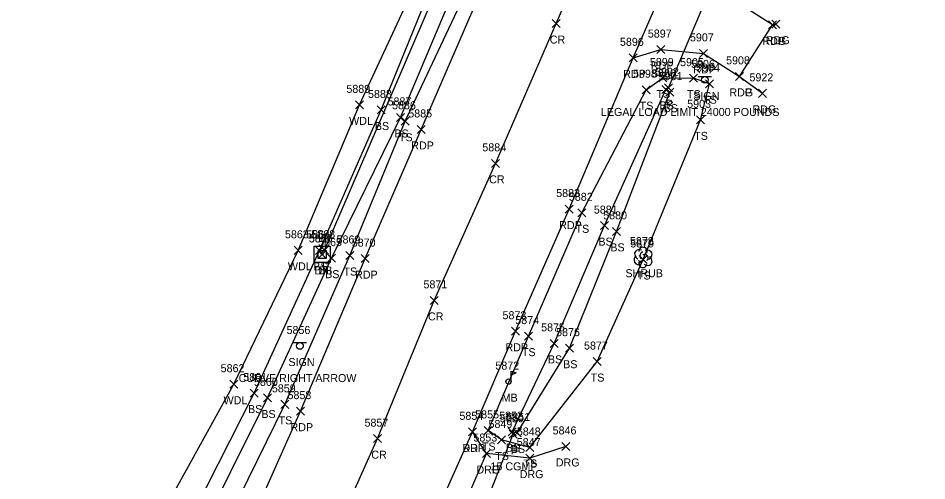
# Model space of a CAD drawing. Extents: x 1611797 to 1633212, y 298978 to 305475.
# Drawn here: x 1622594.7 to 1622821.6, y 301530.3 to 301645.8 of the extents above; entities that cross this region are included whole.
import ezdxf

# ---------------------------------------------------------------- set-up
doc = ezdxf.new("R2010")
doc.units = 0
for name, color, linetype in [('D_A', 7, 'Continuous'), ('D_C', 7, 'Continuous'), ('D_I', 7, 'Continuous'), ('D_TIC', 7, 'Continuous'), ('DCP', 7, 'Continuous'), ('DS', 7, 'Continuous'), ('L_A', 7, 'Continuous'), ('L_I', 7, 'Continuous'), ('L_TIC', 7, 'Continuous'), ('LAWA', 7, 'Continuous'), ('LELB', 7, 'Continuous'), ('LMB', 7, 'Continuous'), ('LSH', 7, 'Continuous'), ('P_A', 7, 'Continuous'), ('P_I', 7, 'Continuous'), ('P_TIC', 7, 'Continuous'), ('PET', 7, 'Continuous'), ('PEU', 7, 'Continuous'), ('PRC', 7, 'Continuous'), ('R_A', 7, 'Continuous'), ('R_I', 7, 'Continuous'), ('R_TIC', 7, 'Continuous'), ('RDG', 7, 'Continuous'), ('RDP', 7, 'Continuous'), ('S_A', 7, 'Continuous'), ('S_C', 7, 'Continuous'), ('S_I', 7, 'Continuous'), ('SSGN', 7, 'Continuous')]:
    doc.layers.add(name, color=color, linetype=linetype)

msp = doc.modelspace()

# ---------------------------------------------------------------- linework, layer by layer
at = {"layer": 'D_TIC'}
for points in [[(1622756.09, 301627.39), (1622758.09, 301629.39)], [(1622758.09, 301627.39), (1622756.09, 301629.39)], [(1622669.61, 301585.77), (1622671.61, 301587.77)], [(1622671.61, 301585.77), (1622669.61, 301587.77)], [(1622670.2, 301586.84), (1622672.2, 301588.84)], [(1622672.2, 301586.84), (1622670.2, 301588.84)], [(1622717.35, 301540.87), (1622719.35, 301542.87)], [(1622719.35, 301540.87), (1622717.35, 301542.87)]]:
    msp.add_lwpolyline(points, dxfattribs=at)
at = {"layer": 'DCP'}
for points in [[(1622671.2, 301587.84), (1622827.38, 301950.3)], [(1622757.09, 301628.39), (1622774.51, 301669.44)], [(1622708.82, 301517.78), (1622718.35, 301541.87)]]:
    msp.add_lwpolyline(points, dxfattribs=at)
at = {"layer": 'DS'}
for p, q in [((1622668.61, 301588.8), (1622672.61, 301588.8)), ((1622668.61, 301584.8), (1622668.61, 301588.8)), ((1622669.61, 301585.8), (1622669.61, 301587.8)), ((1622669.61, 301587.8), (1622671.61, 301587.8)), ((1622671.61, 301587.8), (1622671.61, 301585.8)), ((1622672.61, 301588.8), (1622672.61, 301584.8)), ((1622671.61, 301585.8), (1622669.61, 301585.8)), ((1622670.62, 301586.81), (1622670.62, 301586.81)), ((1622670.62, 301586.81), (1622670.62, 301586.81)), ((1622672.61, 301584.8), (1622668.61, 301584.8))]:
    msp.add_line(p, q, dxfattribs=at)
at = {"layer": 'L_TIC'}
for points in [[(1622754.72, 301629.83), (1622756.72, 301631.83)], [(1622756.72, 301629.83), (1622754.72, 301631.83)], [(1622762.33, 301629.79), (1622764.33, 301631.79)], [(1622764.33, 301629.79), (1622762.33, 301631.79)], [(1622762.33, 301629.79), (1622764.33, 301631.79)], [(1622764.33, 301629.79), (1622762.33, 301631.79)], [(1622750.51, 301626.91), (1622752.51, 301628.91)], [(1622752.51, 301626.91), (1622750.51, 301628.91)], [(1622755.42, 301626.98), (1622757.42, 301628.98)], [(1622757.42, 301626.98), (1622755.42, 301628.98)], [(1622766.34, 301628.41), (1622768.34, 301630.41)], [(1622768.34, 301628.41), (1622766.34, 301630.41)], [(1622756.45, 301626.29), (1622758.45, 301628.29)], [(1622758.45, 301626.29), (1622756.45, 301628.29)], [(1622756.45, 301626.29), (1622758.45, 301628.29)], [(1622758.45, 301626.29), (1622756.45, 301628.29)], [(1622678.92, 301623.12), (1622680.92, 301625.12)], [(1622680.92, 301623.12), (1622678.92, 301625.12)], [(1622684.32, 301621.84), (1622686.32, 301623.84)], [(1622686.32, 301621.84), (1622684.32, 301623.84)], [(1622689.2, 301619.98), (1622691.2, 301621.98)], [(1622691.2, 301619.98), (1622689.2, 301621.98)], [(1622690.37, 301619.02), (1622692.37, 301621.02)], [(1622692.37, 301619.02), (1622690.37, 301621.02)], [(1622764.11, 301619.38), (1622766.11, 301621.38)], [(1622766.11, 301619.38), (1622764.11, 301621.38)], [(1622734.48, 301596.17), (1622736.48, 301598.17)], [(1622736.48, 301596.17), (1622734.48, 301598.17)], [(1622740.16, 301592.97), (1622742.16, 301594.97)], [(1622742.16, 301592.97), (1622740.16, 301594.97)], [(1622743.14, 301591.54), (1622745.14, 301593.54)], [(1622745.14, 301591.54), (1622743.14, 301593.54)], [(1622663.62, 301586.8), (1622665.62, 301588.8)], [(1622665.62, 301586.8), (1622663.62, 301588.8)], [(1622668.95, 301586.77), (1622670.95, 301588.77)], [(1622670.95, 301586.77), (1622668.95, 301588.77)], [(1622671.9, 301584.85), (1622673.9, 301586.85)], [(1622673.9, 301584.85), (1622671.9, 301586.85)], [(1622676.51, 301585.51), (1622678.51, 301587.51)], [(1622678.51, 301585.51), (1622676.51, 301587.51)], [(1622749.82, 301584.52), (1622751.82, 301586.52)], [(1622751.82, 301584.52), (1622749.82, 301586.52)], [(1622721.1, 301565.38), (1622723.1, 301567.38)], [(1622723.1, 301565.38), (1622721.1, 301567.38)], [(1622727.55, 301563.57), (1622729.55, 301565.57)], [(1622729.55, 301563.57), (1622727.55, 301565.57)], [(1622731.34, 301562.37), (1622733.34, 301564.37)], [(1622733.34, 301562.37), (1622731.34, 301564.37)], [(1622738.27, 301559.03), (1622740.27, 301561.03)], [(1622740.27, 301559.03), (1622738.27, 301561.03)], [(1622647.55, 301553.37), (1622649.55, 301555.37)], [(1622649.55, 301553.37), (1622647.55, 301555.37)], [(1622652.65, 301551.16), (1622654.65, 301553.16)], [(1622654.65, 301551.16), (1622652.65, 301553.16)], [(1622655.97, 301549.94), (1622657.97, 301551.94)], [(1622657.97, 301549.94), (1622655.97, 301551.94)], [(1622660.31, 301548.35), (1622662.31, 301550.35)], [(1622662.31, 301548.35), (1622660.31, 301550.35)], [(1622711.09, 301541.83), (1622713.09, 301543.83)], [(1622713.09, 301541.83), (1622711.09, 301543.83)], [(1622717.06, 301541.52), (1622719.06, 301543.52)], [(1622719.06, 301541.52), (1622717.06, 301543.52)], [(1622718.29, 301541.2), (1622720.29, 301543.2)], [(1622720.29, 301541.2), (1622718.29, 301543.2)], [(1622718.29, 301541.2), (1622720.29, 301543.2)], [(1622720.29, 301541.2), (1622718.29, 301543.2)], [(1622714.42, 301539.45), (1622716.42, 301541.45)], [(1622716.42, 301539.45), (1622714.42, 301541.45)], [(1622721.49, 301537.57), (1622723.49, 301539.57)], [(1622723.49, 301537.57), (1622721.49, 301539.57)], [(1622721.49, 301537.57), (1622723.49, 301539.57)], [(1622723.49, 301537.57), (1622721.49, 301539.57)]]:
    msp.add_lwpolyline(points, dxfattribs=at)
at = {"layer": 'LAWA'}
msp.add_lwpolyline([(1622629.31, 301519.57), (1622648.55, 301554.37), (1622664.62, 301587.8), (1622679.92, 301624.12), (1622695.98, 301658.78), (1622711.22, 301695.78), (1622726.95, 301734.16), (1622740.87, 301768.52), (1622755.14, 301811.42), (1622771.04, 301843.63), (1622788.09, 301881.91), (1622808.18, 301922.72), (1622823.47, 301955.6), (1622839.78, 301995.94), (1622853.69, 302036.53), (1622871.34, 302077.8), (1622889.2, 302115.36), (1622900.36, 302148.59), (1622922.7, 302194.91), (1622935.02, 302227), (1622955.61, 302269.3), (1622974.66, 302322.11)], dxfattribs=at)
at = {"layer": 'LELB'}
for points in [[(1622643, 301512.06), (1622661.31, 301549.35), (1622677.51, 301586.51), (1622691.37, 301620.02), (1622707.1, 301653.53), (1622721.75, 301687.85), (1622737.9, 301726.61), (1622754.91, 301765.49), (1622771.04, 301804.05), (1622784.95, 301836.58), (1622802.84, 301876.81), (1622819.3, 301916.18), (1622833.77, 301948.78), (1622851.03, 301989.78), (1622867.88, 302029.76), (1622885.49, 302071.56), (1622902.14, 302111.43), (1622917.02, 302143.8), (1622935.82, 302186.87), (1622950.2, 302222.12), (1622969.04, 302263.04)], [(1622594.68, 301439.81), (1622595.31, 301437.14), (1622596.39, 301436.56), (1622598.61, 301436.87), (1622605.11, 301452.44), (1622623.3, 301484.96), (1622638.71, 301514.37), (1622656.97, 301550.94), (1622672.9, 301585.85), (1622690.2, 301620.98), (1622704.33, 301654.63), (1622718.47, 301691.01), (1622735.69, 301728.38), (1622751, 301766.72), (1622767.76, 301805.21), (1622781.52, 301838.57), (1622799.78, 301877.75), (1622815.96, 301917.88), (1622831.89, 301949.85), (1622847.11, 301991.62), (1622864.58, 302030.86), (1622881.19, 302073.91), (1622897.69, 302112.61), (1622900.36, 302148.59)], [(1622594.68, 301439.81), (1622601.87, 301453.13), (1622619.23, 301487.68), (1622635.73, 301516.83), (1622653.65, 301552.16), (1622669.95, 301587.77), (1622685.32, 301622.84), (1622699.32, 301657.33), (1622714.74, 301693.53), (1622730.88, 301731.3), (1622746.12, 301769.47), (1622759.32, 301807.94), (1622775.78, 301841.76), (1622793.88, 301879.63), (1622811.29, 301920.97), (1622825.77, 301951.79), (1622844.08, 301994.2), (1622859.8, 302033.13), (1622878.46, 302076.5), (1622894.74, 302113.74), (1622900.36, 302148.59)], [(1622722.49, 301538.57), (1622715.42, 301540.45), (1622712.09, 301542.83), (1622722.1, 301566.38), (1622735.48, 301597.17), (1622751.51, 301627.91), (1622755.72, 301630.83), (1622763.33, 301630.79)], [(1622722.49, 301538.57), (1622739.27, 301560.03), (1622750.82, 301585.52), (1622765.11, 301620.38), (1622767.34, 301629.41), (1622763.33, 301630.79)], [(1622719.29, 301542.2), (1622718.06, 301542.52), (1622728.55, 301564.57), (1622741.16, 301593.97), (1622756.42, 301627.98), (1622757.45, 301627.29)], [(1622719.29, 301542.2), (1622732.34, 301563.37), (1622744.14, 301592.54), (1622757.45, 301627.29)]]:
    msp.add_lwpolyline(points, dxfattribs=at)
at = {"layer": 'LMB'}
for p, q in [((1622717.78, 301557.62), (1622719.08, 301557.24)), ((1622717.79, 301555.03), (1622717.79, 301557.62)), ((1622717.79, 301556.72), (1622719.07, 301557.23)), ((1622717.13, 301555.02), (1622717.13, 301555.02))]:
    msp.add_line(p, q, dxfattribs=at)
msp.add_circle((1622717.13, 301555.02), 0.656, dxfattribs=at)
at = {"layer": 'LSH'}
msp.add_line((1622750.73, 301586.09), (1622750.73, 301586.09), dxfattribs=at)
msp.add_line((1622750.73, 301586.09), (1622750.73, 301586.09), dxfattribs=at)
msp.add_arc((1622750.77, 301587.52), 1.05, 335.5272, 180.9563, dxfattribs=at)
for centre, major_axis, ratio, start_param, end_param in [((1622749.94, 301586.76), (1.21, -0.51), 0.895232, 1.570796, 4.712389), ((1622751.77, 301586.67), (-1.14, -0.48), 0.949671, 1.570796, 4.712389), ((1622749.64, 301585.38), (0.58, -1.04), 0.959034, 3.141593, 6.283185), ((1622750.27, 301585.34), (-0.625, -0.083), 0.423636, 0, 3.141593), ((1622750.52, 301586.55), (-0.208, -0.792), 0.645439, 3.141593, 6.283185), ((1622751.23, 301585.92), (-0.5, 0.667), 0.989748, 3.141593, 6.283185), ((1622751.73, 301585.26), (-1.09, 0.79), 0.841452, 1.570796, 4.712389), ((1622750.73, 301584.59), (0.26, 1.06), 0.942809, 1.570796, 4.712389)]:
    msp.add_ellipse(centre, major_axis=major_axis, ratio=ratio, start_param=start_param, end_param=end_param, dxfattribs=at)
at = {"layer": 'P_TIC'}
for points in [[(1622728.01, 301643.42), (1622730.01, 301645.42)], [(1622730.01, 301643.42), (1622728.01, 301645.42)], [(1622782.06, 301643.09), (1622784.06, 301645.09)], [(1622784.06, 301643.09), (1622782.06, 301645.09)], [(1622782.06, 301643.09), (1622784.06, 301645.09)], [(1622784.06, 301643.09), (1622782.06, 301645.09)], [(1622782.95, 301643.26), (1622784.95, 301645.26)], [(1622784.95, 301643.26), (1622782.95, 301645.26)], [(1622754.21, 301636.93), (1622756.21, 301638.93)], [(1622756.21, 301636.93), (1622754.21, 301638.93)], [(1622764.81, 301635.97), (1622766.81, 301637.97)], [(1622766.81, 301635.97), (1622764.81, 301637.97)], [(1622747.3, 301634.86), (1622749.3, 301636.86)], [(1622749.3, 301634.86), (1622747.3, 301636.86)], [(1622747.3, 301634.86), (1622749.3, 301636.86)], [(1622749.3, 301634.86), (1622747.3, 301636.86)], [(1622773.83, 301630.24), (1622775.83, 301632.24)], [(1622775.83, 301630.24), (1622773.83, 301632.24)], [(1622773.83, 301630.24), (1622775.83, 301632.24)], [(1622775.83, 301630.24), (1622773.83, 301632.24)], [(1622779.59, 301626), (1622781.59, 301628)], [(1622781.59, 301626), (1622779.59, 301628)], [(1622694.37, 301616.98), (1622696.37, 301618.98)], [(1622696.37, 301616.98), (1622694.37, 301618.98)], [(1622712.87, 301608.52), (1622714.87, 301610.52)], [(1622714.87, 301608.52), (1622712.87, 301610.52)], [(1622731.31, 301597.1), (1622733.31, 301599.1)], [(1622733.31, 301597.1), (1622731.31, 301599.1)], [(1622680.33, 301584.73), (1622682.33, 301586.73)], [(1622682.33, 301584.73), (1622680.33, 301586.73)], [(1622697.59, 301574.31), (1622699.59, 301576.31)], [(1622699.59, 301574.31), (1622697.59, 301576.31)], [(1622717.91, 301566.6), (1622719.91, 301568.6)], [(1622719.91, 301566.6), (1622717.91, 301568.6)], [(1622664.21, 301546.65), (1622666.21, 301548.65)], [(1622666.21, 301546.65), (1622664.21, 301548.65)], [(1622707.15, 301541.48), (1622709.15, 301543.48)], [(1622709.15, 301541.48), (1622707.15, 301543.48)], [(1622683.44, 301539.78), (1622685.44, 301541.78)], [(1622685.44, 301539.78), (1622683.44, 301541.78)]]:
    msp.add_lwpolyline(points, dxfattribs=at)
at = {"layer": 'PET'}
for points in [[(1622648.26, 301509.67), (1622665.21, 301547.65), (1622681.33, 301585.73), (1622695.37, 301617.98), (1622710.24, 301652.42), (1622725.24, 301685.81), (1622742.04, 301725.41), (1622758.88, 301763.93), (1622775.24, 301802.31), (1622789.18, 301834.69), (1622806.59, 301875.58), (1622823.24, 301913.81), (1622837.58, 301947.53), (1622854.56, 301988.08), (1622872.12, 302028.45), (1622889.38, 302069.51), (1622906.69, 302110.12), (1622920.84, 302142.69), (1622939.57, 302184.64), (1622954.91, 302220.6), (1622972.44, 302261.85)], [(1622698.78, 301521.43), (1622708.15, 301542.48), (1622718.91, 301567.6), (1622732.31, 301598.1), (1622748.3, 301635.86), (1622762.96, 301669.6), (1622778.35, 301705.89), (1622784.3, 301719.76), (1622791.39, 301735.05), (1622795.53, 301745.68), (1622812.78, 301786.17), (1622826.49, 301818.45), (1622843.67, 301858.56), (1622860.37, 301897.43), (1622876.1, 301933.63), (1622891.74, 301969.78), (1622909.96, 302011.85), (1622927.46, 302052.61), (1622945.32, 302094.8), (1622972.71, 302158.13)], [(1622748.3, 301635.86), (1622755.21, 301637.93), (1622765.81, 301636.97), (1622774.83, 301631.24), (1622783.06, 301644.09), (1622772.18, 301651.11), (1622766.22, 301657.88), (1622762.96, 301669.6)]]:
    msp.add_lwpolyline(points, dxfattribs=at)
at = {"layer": 'PEU'}
for points in [[(1622783.06, 301644.09), (1622783.95, 301644.26)], [(1622774.83, 301631.24), (1622780.59, 301627)]]:
    msp.add_lwpolyline(points, dxfattribs=at)
at = {"layer": 'PRC'}
msp.add_lwpolyline([(1622666.77, 301501.34), (1622684.44, 301540.78), (1622698.59, 301575.31), (1622713.87, 301609.52), (1622729.01, 301644.42), (1622743.12, 301676.89), (1622759.85, 301716.06), (1622777.36, 301756.12), (1622793.76, 301794.22), (1622808.13, 301826.76), (1622825.32, 301867.31), (1622841.48, 301905.46), (1622856.61, 301940.95), (1622872.28, 301978.08), (1622890.25, 302020.71), (1622907.64, 302061.05), (1622925.87, 302103.21), (1622941.24, 302138.62), (1622957.15, 302175.75), (1622973.3, 302212.68)], dxfattribs=at)
at = {"layer": 'R_TIC'}
for points in [[(1622707.15, 301541.48), (1622709.15, 301543.48)], [(1622709.15, 301541.48), (1622707.15, 301543.48)], [(1622710.64, 301536.06), (1622712.64, 301538.06)], [(1622712.64, 301536.06), (1622710.64, 301538.06)], [(1622710.64, 301536.06), (1622712.64, 301538.06)], [(1622712.64, 301536.06), (1622710.64, 301538.06)], [(1622730.47, 301537.84), (1622732.47, 301539.84)], [(1622732.47, 301537.84), (1622730.47, 301539.84)], [(1622721.45, 301534.92), (1622723.45, 301536.92)], [(1622723.45, 301534.92), (1622721.45, 301536.92)]]:
    msp.add_lwpolyline(points, dxfattribs=at)
at = {"layer": 'RDG'}
msp.add_lwpolyline([(1622731.47, 301538.84), (1622722.45, 301535.92), (1622711.64, 301537.06)], dxfattribs=at)
at = {"layer": 'RDP'}
msp.add_lwpolyline([(1622698.78, 301521.43), (1622705.35, 301522.4), (1622711.64, 301537.06), (1622708.15, 301542.48)], dxfattribs=at)
at = {"layer": 'SSGN'}
for p, q in [((1622764.51, 301631.2), (1622767.85, 301631.2)), ((1622766.16, 301630.37), (1622766.16, 301630.37)), ((1622663.4, 301564.76), (1622666.73, 301564.76)), ((1622665.05, 301563.93), (1622665.05, 301563.93))]:
    msp.add_line(p, q, dxfattribs=at)
for centre in [(1622766.16, 301630.37), (1622665.05, 301563.93)]:
    msp.add_circle(centre, 0.833, dxfattribs=at)

# ---------------------------------------------------------------- texts
at = {"layer": 'D_A'}
for s, p in [('P', (1622756.46, 301623.39)), ('DIB', (1622668.71, 301581.77)), ('DI', (1622669.67, 301581.81)), ('P', (1622670.58, 301582.84)), ('P', (1622717.72, 301536.87))]:
    msp.add_text(s, height=2, dxfattribs=at).set_placement(p)
at = {"layer": 'D_C'}
msp.add_text('15 CGMP', height=2, dxfattribs=at).set_placement((1622712.64, 301532.87))
at = {"layer": 'D_I'}
for s, p in [('5902', (1622753.75, 301631.39)), ('5868', (1622667.9, 301590.84)), ('5866', (1622667.25, 301589.81)), ('5867', (1622667.3, 301589.77)), ('5850', (1622715, 301544.87))]:
    msp.add_text(s, height=2, dxfattribs=at).set_placement(p)
at = {"layer": 'L_A'}
for s, p in [('TS', (1622754.13, 301625.83)), ('TS', (1622761.74, 301625.79)), ('TS', (1622761.74, 301625.79)), ('TS', (1622765.75, 301624.41)), ('TS', (1622749.92, 301622.91)), ('BS', (1622754.86, 301622.98)), ('BS', (1622755.89, 301622.29)), ('BS', (1622755.89, 301622.29)), ('WDL', (1622677.34, 301619.12)), ('BS', (1622683.76, 301617.84)), ('BS', (1622688.64, 301615.98)), ('TS', (1622763.52, 301615.38)), ('TS', (1622689.78, 301615.02)), ('TS', (1622733.89, 301592.17)), ('BS', (1622739.6, 301588.97)), ('BS', (1622742.58, 301587.54)), ('WDL', (1622662.04, 301582.8)), ('BS', (1622668.39, 301582.77)), ('TS', (1622675.92, 301581.51)), ('BS', (1622671.34, 301580.85)), ('SHRUB', (1622746.36, 301581.09)), ('TS', (1622749.23, 301580.52)), ('TS', (1622720.5, 301561.38)), ('BS', (1622726.99, 301559.57)), ('BS', (1622730.78, 301558.37)), ('TS', (1622737.68, 301555.03)), ('WDL', (1622645.97, 301549.37)), ('MB', (1622715.44, 301550.02)), ('BS', (1622652.09, 301547.16)), ('BS', (1622655.41, 301545.94)), ('TS', (1622659.72, 301544.35)), ('TS', (1622710.5, 301537.83)), ('BS', (1622716.5, 301537.52)), ('BS', (1622717.73, 301537.2)), ('BS', (1622717.73, 301537.2)), ('TS', (1622713.83, 301535.45)), ('TS', (1622720.9, 301533.57)), ('TS', (1622720.9, 301533.57))]:
    msp.add_text(s, height=2, dxfattribs=at).set_placement(p)
at = {"layer": 'L_I'}
for s, p in [('5899', (1622752.45, 301633.83)), ('5905', (1622759.99, 301633.79)), ('5905', (1622759.99, 301633.79)), ('5904', (1622764, 301632.41)), ('5898', (1622748.25, 301630.91)), ('5900', (1622753, 301630.98)), ('5901', (1622754.68, 301630.29)), ('5901', (1622754.68, 301630.29)), ('5889', (1622676.65, 301627.12)), ('5888', (1622682.06, 301625.84)), ('5887', (1622686.94, 301623.98)), ('5886', (1622688.06, 301623.02)), ('5903', (1622761.77, 301623.38)), ('5882', (1622732.22, 301600.17)), ('5881', (1622738.46, 301596.97)), ('5880', (1622740.79, 301595.54)), ('5863', (1622661.31, 301590.8)), ('5864', (1622666.64, 301590.77)), ('5865', (1622669.59, 301588.85)), ('5869', (1622674.2, 301589.51)), ('5878', (1622747.47, 301589.09)), ('5879', (1622747.55, 301588.52)), ('5874', (1622718.84, 301569.38)), ('5875', (1622725.29, 301567.57)), ('5876', (1622729.03, 301566.37)), ('5877', (1622736.01, 301563.03)), ('5862', (1622645.25, 301557.37)), ('5872', (1622713.87, 301558.02)), ('5861', (1622650.91, 301555.16)), ('5860', (1622653.57, 301553.94)), ('5859', (1622658.04, 301552.35)), ('5855', (1622708.83, 301545.83)), ('5852', (1622714.8, 301545.52)), ('5851', (1622716.59, 301545.2)), ('5851', (1622716.59, 301545.2)), ('5849', (1622712.15, 301543.45)), ('5848', (1622719.23, 301541.57)), ('5848', (1622719.23, 301541.57))]:
    msp.add_text(s, height=2, dxfattribs=at).set_placement(p)
at = {"layer": 'P_A'}
for s, p in [('CR', (1622727.45, 301639.42)), ('RDG', (1622780.55, 301639.09)), ('RDP', (1622780.55, 301639.09)), ('RDG', (1622781.43, 301639.26)), ('RDP', (1622752.7, 301632.93)), ('RDP', (1622763.29, 301631.97)), ('RDP', (1622745.79, 301630.86)), ('RDP', (1622745.79, 301630.86)), ('RDG', (1622772.31, 301626.24)), ('RDP', (1622772.31, 301626.24)), ('RDG', (1622778.08, 301622)), ('RDP', (1622692.86, 301612.98)), ('CR', (1622712.31, 301604.52)), ('RDP', (1622729.8, 301593.1)), ('RDP', (1622678.82, 301580.73)), ('CR', (1622697.03, 301570.31)), ('RDP', (1622716.39, 301562.6)), ('RDP', (1622662.7, 301542.65)), ('CR', (1622682.87, 301535.78)), ('RDP', (1622705.64, 301537.48))]:
    msp.add_text(s, height=2, dxfattribs=at).set_placement(p)
at = {"layer": 'P_I'}
for s, p in [('5897', (1622751.95, 301640.93)), ('5896', (1622744.98, 301638.86)), ('5896', (1622744.98, 301638.86)), ('5907', (1622762.47, 301639.97)), ('5908', (1622771.49, 301634.24)), ('5908', (1622771.49, 301634.24)), ('5922', (1622777.33, 301630)), ('5885', (1622692.11, 301620.98)), ('5884', (1622710.61, 301612.52)), ('5883', (1622729.05, 301601.1)), ('5870', (1622677.99, 301588.73)), ('5871', (1622695.9, 301578.31)), ('5873', (1622715.65, 301570.6)), ('5858', (1622661.95, 301550.65)), ('5854', (1622704.89, 301545.48)), ('5857', (1622681.18, 301543.78))]:
    msp.add_text(s, height=2, dxfattribs=at).set_placement(p)
at = {"layer": 'R_A'}
for s, p in [('DRP', (1622705.64, 301537.48)), ('DRG', (1622728.96, 301533.84)), ('DRG', (1622709.13, 301532.06)), ('DRP', (1622709.13, 301532.06)), ('DRG', (1622719.94, 301530.92))]:
    msp.add_text(s, height=2, dxfattribs=at).set_placement(p)
at = {"layer": 'R_I'}
for s, p in [('5854', (1622704.89, 301545.48)), ('5846', (1622728.16, 301541.84)), ('5853', (1622708.38, 301540.06)), ('5853', (1622708.38, 301540.06)), ('5847', (1622719.2, 301538.92))]:
    msp.add_text(s, height=2, dxfattribs=at).set_placement(p)
at = {"layer": 'S_A'}
for p in [(1622763.3, 301625.35), (1622662.18, 301558.91)]:
    msp.add_text('SIGN', height=2, dxfattribs=at).set_placement(p)
at = {"layer": 'S_C'}
for s, p in [('LEGAL LOAD LIMIT 24000 POUNDS', (1622740.22, 301621.35)), ('CURVE RIGHT ARROW', (1622649.75, 301554.91))]:
    msp.add_text(s, height=2, dxfattribs=at).set_placement(p)
at = {"layer": 'S_I'}
for s, p in [('5906', (1622762.75, 301633.35)), ('5856', (1622661.71, 301566.91))]:
    msp.add_text(s, height=2, dxfattribs=at).set_placement(p)

doc.saveas('drawing.dxf')
